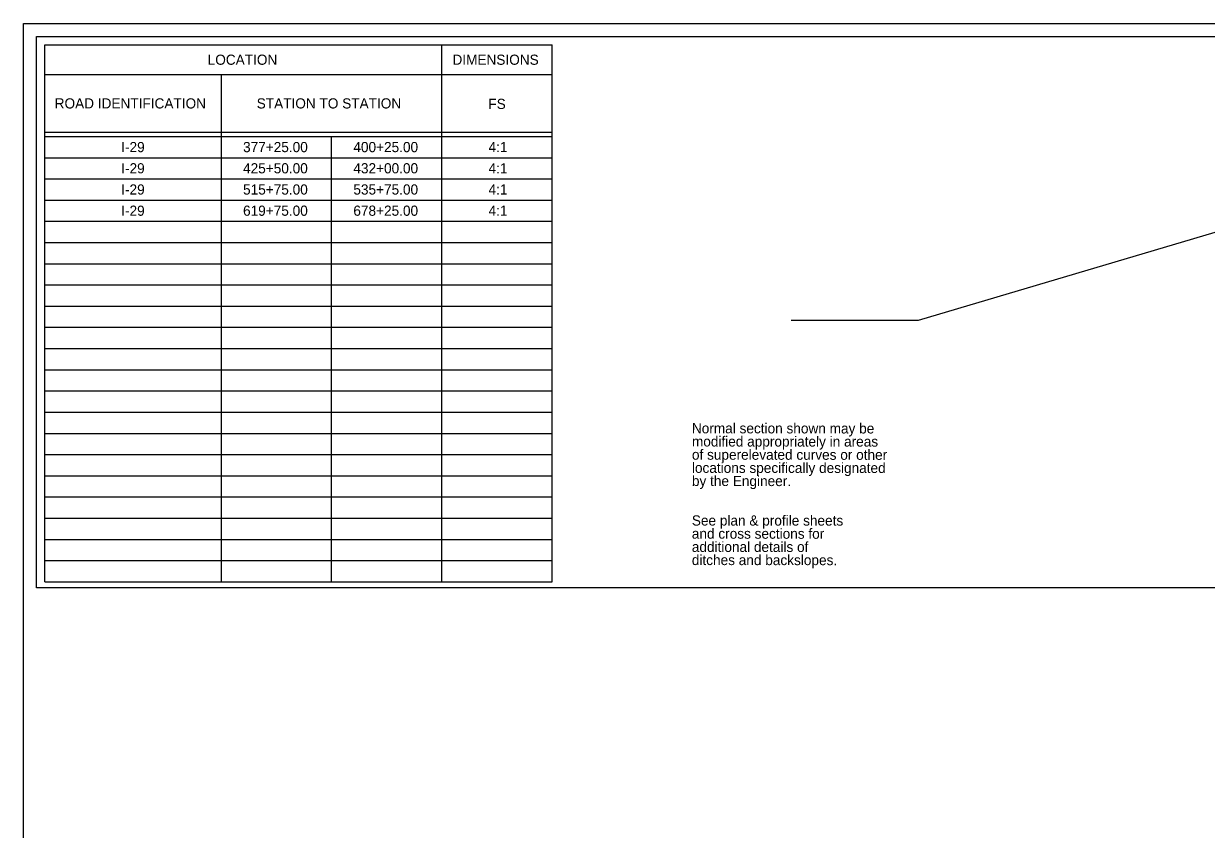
# Model space of a CAD drawing. Extents: x 10133 to 81668, y 6979 to 11018.
# Drawn here: x 10133 to 11526, y 8994 to 9944 of the extents above; entities that cross this region are included whole.
import ezdxf

# ---------------------------------------------------------------- set-up
doc = ezdxf.new("R2010")
doc.units = 0
for name, color, linetype in [('brgPreGradingNew', 7, 'Continuous'), ('brgPreStructureAlternateA', 7, 'Continuous'), ('brgPreStructureNew', 7, 'Continuous'), ('dsnCellElements', 7, 'Continuous'), ('dsnStdPattern', 7, 'Continuous'), ('Level 11', 7, 'Continuous')]:
    doc.layers.add(name, color=color, linetype=linetype)

msp = doc.modelspace()

# ---------------------------------------------------------------- linework, layer by layer
at = {"layer": 'brgPreGradingNew'}
for p, q in [((10157.5, 9919), (10755.5, 9919)), ((10157.5, 9286), (10157.5, 9919)), ((10625.5, 9286), (10625.5, 9919)), ((10755.5, 9286), (10755.5, 9919)), ((10157.5, 9884), (10755.5, 9884)), ((10365.5, 9286), (10365.5, 9884)), ((10157.5, 9816), (10755.5, 9816)), ((10157.5, 9811), (10755.5, 9811)), ((10495.5, 9286), (10495.5, 9811)), ((10157.5, 9786), (10755.5, 9786)), ((10157.5, 9761), (10755.5, 9761)), ((10157.5, 9736), (10755.5, 9736)), ((10157.5, 9711), (10755.5, 9711)), ((10157.5, 9686), (10755.5, 9686)), ((10157.5, 9661), (10755.5, 9661)), ((10157.5, 9636), (10755.5, 9636)), ((10157.5, 9611), (10755.5, 9611)), ((10157.5, 9586), (10755.5, 9586)), ((10157.5, 9561), (10755.5, 9561)), ((10157.5, 9536), (10755.5, 9536)), ((10157.5, 9511), (10755.5, 9511)), ((10157.5, 9486), (10755.5, 9486)), ((10157.5, 9461), (10755.5, 9461)), ((10157.5, 9436), (10755.5, 9436)), ((10157.5, 9411), (10755.5, 9411)), ((10157.5, 9386), (10755.5, 9386)), ((10157.5, 9361), (10755.5, 9361)), ((10157.5, 9336), (10755.5, 9336)), ((10157.5, 9311), (10755.5, 9311)), ((10157.5, 9286), (10755.5, 9286))]:
    msp.add_line(p, q, dxfattribs=at)
at = {"layer": 'brgPreStructureAlternateA'}
for p, q in [((11587.6, 9713), (11186.9, 9594)), ((11186.9, 9594), (11036.9, 9594))]:
    msp.add_line(p, q, dxfattribs=at)
at = {"layer": 'dsnCellElements'}
msp.add_lwpolyline([(10147.5, 9929), (13252.5, 9929), (13252.5, 9279), (10147.5, 9279), (10147.5, 9929)], dxfattribs=at)
at = {"layer": 'Level 11'}
msp.add_lwpolyline([(10132.5, 9944), (13267.5, 9944), (13267.5, 7924), (10132.5, 7924)], close=True, dxfattribs=at)

# ---------------------------------------------------------------- texts
at = {"layer": 'brgPreGradingNew'}
for s, p in [('LOCATION', (10349.4, 9895.5)), ('DIMENSIONS', (10637.9, 9895.5)), ('ROAD IDENTIFICATION', (10169.1, 9844)), ('STATION TO STATION', (10407.2, 9844)), ('I-29', (10247.5, 9792.5)), ('377+25.00', (10391.1, 9792.5)), ('400+25.00', (10521.1, 9792.5)), ('4:1', (10680.4, 9792.5)), ('I-29', (10247.5, 9767.5)), ('425+50.00', (10391.1, 9767.5)), ('432+00.00', (10521.1, 9767.5)), ('4:1', (10680.4, 9767.5)), ('I-29', (10247.5, 9742.5)), ('515+75.00', (10391.1, 9742.5)), ('535+75.00', (10521.1, 9742.5)), ('4:1', (10680.4, 9742.5)), ('I-29', (10247.5, 9717.5)), ('619+75.00', (10391.1, 9717.5)), ('678+25.00', (10521.1, 9717.5)), ('4:1', (10680.4, 9717.5))]:
    msp.add_text(s, height=12, dxfattribs=at).set_placement(p)
at = {"layer": 'brgPreStructureNew'}
msp.add_text('FS', height=12, dxfattribs=at).set_placement((10680.2, 9843.4))
at = {"layer": 'dsnStdPattern'}
for s, p in [('Normal section shown may be', (10920.1, 9461)), ('modified appropriately in areas', (10920.1, 9445.5)), ('of superelevated curves or other', (10920.1, 9429.9)), ('locations specifically designated', (10920.1, 9414.4)), ('by the Engineer.', (10920.1, 9398.9)), ('See plan & profile sheets', (10920, 9352.3)), ('and cross sections for', (10920, 9336.8)), ('additional details of', (10920, 9321.2)), ('ditches and backslopes.', (10920, 9305.7))]:
    msp.add_text(s, height=12, rotation=359.9583, dxfattribs=at).set_placement(p)

doc.saveas('drawing.dxf')
